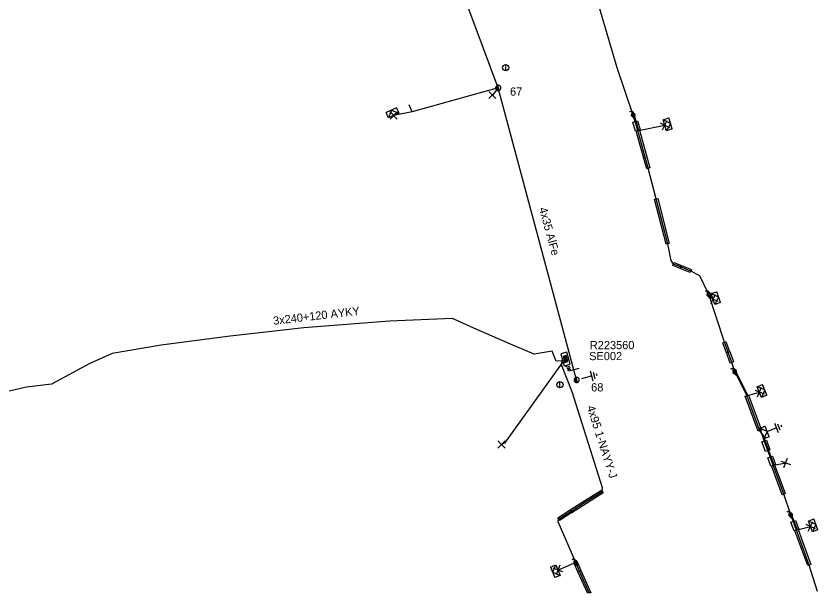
# Model space of a CAD drawing. Extents: x -536149 to -535465, y -1201639 to -1201298.
# Drawn here: x -535608.3 to -535510.8, y -1201637.8 to -1201567.7 of the extents above; entities that cross this region are included whole.
import ezdxf

# ---------------------------------------------------------------- set-up
doc = ezdxf.new("R2010")
doc.units = 0
for name, color, linetype in [('Vrstva 1', 7, 'Continuous'), ('Vrstva 10', 7, 'Continuous'), ('Vrstva 13', 7, 'Continuous'), ('Vrstva 14', 7, 'Continuous'), ('Vrstva 15', 7, 'Continuous'), ('Vrstva 18', 7, 'Continuous'), ('Vrstva 19', 7, 'Continuous'), ('Vrstva 2', 7, 'Continuous'), ('Vrstva 20', 7, 'Continuous'), ('Vrstva 28', 7, 'Continuous'), ('Vrstva 29', 7, 'Continuous'), ('Vrstva 30', 7, 'Continuous'), ('Vrstva 31', 7, 'Continuous'), ('Vrstva 34', 7, 'Continuous'), ('Vrstva 36', 7, 'Continuous'), ('Vrstva 4', 7, 'Continuous'), ('Vrstva 5', 7, 'Continuous'), ('Vrstva 52', 7, 'Continuous'), ('Vrstva 59', 7, 'Continuous'), ('Vrstva 6', 7, 'Continuous'), ('Vrstva 8', 7, 'Continuous'), ('Vrstva 9', 7, 'Continuous')]:
    doc.layers.add(name, color=color, linetype=linetype)

# ---------------------------------------------------------------- blocks, each defined once
blk = doc.blocks.new('NN440')
at = {"layer": 'Vrstva 2'}
for points in [[(0.63, 0), (0.63, 0.06), (0.62, 0.13), (0.6, 0.19), (0.58, 0.25), (0.55, 0.31), (0.51, 0.37), (0.47, 0.42), (0.42, 0.46), (0.37, 0.51), (0.32, 0.54), (0.26, 0.57), (0.2, 0.59), (0.13, 0.61), (0.07, 0.62), (0, 0.63), (-0.06, 0.62), (-0.13, 0.61), (-0.19, 0.59), (-0.26, 0.57), (-0.31, 0.54), (-0.37, 0.51), (-0.42, 0.46), (-0.47, 0.42), (-0.51, 0.37), (-0.54, 0.31), (-0.57, 0.25), (-0.6, 0.19), (-0.62, 0.13), (-0.63, 0.06), (-0.63, 0), (-0.63, -0.07), (-0.62, -0.14), (-0.6, -0.2), (-0.57, -0.26), (-0.54, -0.32), (-0.51, -0.37), (-0.47, -0.43), (-0.42, -0.47), (-0.37, -0.51), (-0.31, -0.55), (-0.26, -0.58), (-0.19, -0.6), (-0.13, -0.62), (-0.06, -0.63), (0, -0.63), (0.07, -0.63), (0.13, -0.62), (0.2, -0.6), (0.26, -0.58), (0.32, -0.55), (0.37, -0.51), (0.42, -0.47), (0.47, -0.43), (0.51, -0.37), (0.55, -0.32), (0.58, -0.26), (0.6, -0.2), (0.62, -0.14), (0.63, -0.07), (0.63, 0)], [(-0.63, 0), (0.63, 0)], [(-0.6, -0.18), (0.57, -0.18)], [(-0.51, -0.32), (0.5, -0.32)], [(-0.37, -0.47), (0.35, -0.47)]]:
    blk.add_lwpolyline(points, dxfattribs=at)
blk = doc.blocks.new('NN840')
at = {"layer": 'Vrstva 15'}
for points in [[(0.003, 0.619), (0.003, -0.631)], [(-0.745, -0.71), (-0.745, -0.66)], [(-0.73, -0.764), (-0.745, -0.71)], [(-0.657, -0.798), (-0.73, -0.764)], [(-0.627, -0.798), (-0.657, -0.798)], [(-0.558, -0.764), (-0.627, -0.798)], [(-0.538, -0.71), (-0.558, -0.764)], [(-0.538, -0.385), (-0.538, -0.71)], [(-0.332, -0.385), (-0.332, -0.798)], [(-0.332, -0.641), (-0.125, -0.385)], [(-0.263, -0.557), (-0.091, -0.798)]]:
    blk.add_lwpolyline(points, dxfattribs=at)
blk = doc.blocks.new('NN770')
at = {"layer": 'Vrstva 10'}
for p, q in [((0.002, 0.187), (0.002, 0.263)), ((0.002, -0.276), (0.002, 0.111))]:
    blk.add_line(p, q, dxfattribs=at)
blk.add_circle((0, -0.008), 0.375, dxfattribs=at)
blk = doc.blocks.new('NN880')
at = {"layer": 'Vrstva 4'}
for points in [[(0.001, 0.248), (-0.499, 0)], [(0.001, 0.185), (-0.373, 0)], [(0.001, 0.122), (-0.247, 0)], [(0.001, 0.059), (-0.125, 0)], [(0.501, 0), (0.001, 0.248)], [(0.375, 0), (0.001, 0.185)], [(0.249, 0), (0.001, 0.122)], [(0.127, 0), (0.001, 0.059)], [(-0.566, -0.13), (-0.436, -0.13)], [(-0.499, 0), (0.001, -0.252)], [(-0.499, -0.13), (-0.499, -0.327)], [(-0.373, 0), (0.001, -0.189)], [(-0.247, 0), (0.001, -0.126)], [(-0.125, 0), (0.001, -0.063)], [(0.001, -0.252), (0.501, 0)], [(0.001, -0.189), (0.375, 0)], [(0.001, -0.126), (0.249, 0)], [(0.001, -0.063), (0.127, 0)]]:
    blk.add_lwpolyline(points, dxfattribs=at)
blk = doc.blocks.new('NN800')
at = {"layer": 'Vrstva 1'}
for points in [[(-0.442, 0.442), (0.442, -0.442)], [(-0.442, -0.442), (0.442, 0.442)]]:
    blk.add_lwpolyline(points, dxfattribs=at)
blk = doc.blocks.new('NN620')
at = {"layer": 'Vrstva 8'}
for points in [[(0.752, 0.004), (-0.748, 0.004)], [(-0.748, 0.004), (-0.748, -0.746)], [(0.752, -0.746), (0.752, 0.004)], [(-0.748, -0.746), (0.752, -0.746)], [(0.368, -0.18), (-0.376, -0.18)], [(-0.376, -0.18), (-0.376, -0.558)], [(-0.376, -0.558), (0.368, -0.558)], [(0.321, -0.227), (-0.329, -0.227)], [(-0.329, -0.227), (-0.329, -0.51)], [(-0.329, -0.51), (0.321, -0.51)], [(0.274, -0.274), (-0.281, -0.274)], [(-0.281, -0.274), (-0.281, -0.463)], [(-0.281, -0.463), (0.274, -0.463)], [(0.227, -0.321), (-0.234, -0.321)], [(-0.234, -0.321), (-0.234, -0.416)], [(-0.234, -0.416), (0.227, -0.416)], [(-0.193, -0.369), (0.185, -0.369)], [(0.227, -0.416), (0.227, -0.321)], [(0.274, -0.463), (0.274, -0.274)], [(0.321, -0.51), (0.321, -0.227)], [(0.368, -0.558), (0.368, -0.18)]]:
    blk.add_lwpolyline(points, dxfattribs=at)
blk = doc.blocks.new('NN630')
at = {"layer": 'Vrstva 9'}
for points in [[(-0.003, -0.7), (-0.703, 0)], [(-0.703, -0.7), (-0.703, 0), (0.697, 0), (0.697, -0.7)], [(-0.703, -0.7), (0.697, -0.7)], [(-0.003, -0.7), (0.697, 0)]]:
    blk.add_lwpolyline(points, dxfattribs=at)
blk = doc.blocks.new('NN810')
at = {"layer": 'Vrstva 14'}
for points in [[(0.004, -0.64), (0.004, -1.89)], [(0.629, -1.89), (-0.621, -1.89)], [(0.388, -2.2), (-0.399, -2.2)], [(0.004, -2.515), (-0.124, -2.515)], [(0.137, -2.515), (0.004, -2.515)]]:
    blk.add_lwpolyline(points, dxfattribs=at)
blk = doc.blocks.new('NN510')
at = {"layer": 'Vrstva 2'}
blk.add_lwpolyline([(0.001, 0.002), (0.001, 0.939)], dxfattribs=at)

msp = doc.modelspace()

# ---------------------------------------------------------------- linework, layer by layer
at = {"layer": 'Vrstva 1'}
msp.add_lwpolyline([(-535540.143, -1201611.931), (-535549.68, -1201576.4), (-535561.545, -1201544.626)], dxfattribs=at)
at = {"layer": 'Vrstva 20'}
for points in [[(-535532.743, -1201580.414), (-535532.413, -1201581.514), (-535532.987, -1201581.686), (-535533.317, -1201580.586)], [(-535531.623, -1201586.243), (-535532.893, -1201581.653), (-535532.507, -1201581.547), (-535531.237, -1201586.137)], [(-535529.264, -1201595.43), (-535530.664, -1201589.96), (-535530.276, -1201589.86), (-535528.876, -1201595.33)], [(-535528.311, -1201597.652), (-535527.391, -1201597.992), (-535527.529, -1201598.368), (-535528.449, -1201598.028)], [(-535526.317, -1201598.875), (-535527.537, -1201598.365), (-535527.383, -1201597.995), (-535526.163, -1201598.505)], [(-535521.993, -1201607.268), (-535521.533, -1201608.468), (-535521.907, -1201608.612), (-535522.367, -1201607.412)], [(-535521.459, -1201609.877), (-535521.909, -1201608.607), (-535521.531, -1201608.473), (-535521.081, -1201609.743)], [(-535519.252, -1201613.761), (-535517.672, -1201618.031), (-535518.048, -1201618.169), (-535519.628, -1201613.899)], [(-535517.058, -1201619.247), (-535516.628, -1201620.417), (-535517.192, -1201620.623), (-535517.622, -1201619.453)], [(-535516.338, -1201621.179), (-535515.968, -1201622.209), (-535516.532, -1201622.411), (-535516.902, -1201621.381)], [(-535515.137, -1201625.88), (-535516.437, -1201622.38), (-535516.063, -1201622.24), (-535514.763, -1201625.74)], [(-535540.928, -1201627.731), (-535539.157, -1201626.601), (-535537.136, -1201625.331), (-535536.924, -1201625.669), (-535538.943, -1201626.939), (-535540.712, -1201628.069)], [(-535542.438, -1201628.702), (-535540.928, -1201627.732), (-535540.712, -1201628.068), (-535542.222, -1201629.038)], [(-535513.529, -1201629.015), (-535513.129, -1201630.085), (-535513.691, -1201630.295), (-535514.091, -1201629.225)], [(-535512.038, -1201634.509), (-535513.598, -1201630.259), (-535513.222, -1201630.121), (-535511.662, -1201634.371)], [(-535540.066, -1201634.051), (-535539.616, -1201635.101), (-535539.984, -1201635.259), (-535540.434, -1201634.209)], [(-535538.836, -1201637.835), (-535539.983, -1201635.261), (-535539.617, -1201635.099), (-535538.399, -1201637.832)]]:
    msp.add_lwpolyline(points, close=True, dxfattribs=at)
at = {"layer": 'Vrstva 5'}
for points in [[(-535510.853, -1201637.663), (-535511.85, -1201634.44), (-535513.41, -1201630.19), (-535514.11, -1201628.34), (-535514.95, -1201625.81), (-535516.25, -1201622.31), (-535516.62, -1201621.28), (-535517.34, -1201619.35), (-535517.62, -1201618.44), (-535517.86, -1201618.1), (-535519.44, -1201613.83), (-535520.91, -1201610.91), (-535521.27, -1201609.81), (-535521.72, -1201608.54), (-535522.18, -1201607.34), (-535524.06, -1201601.54), (-535525.16, -1201599.28), (-535526.24, -1201598.69), (-535527.46, -1201598.18), (-535528.38, -1201597.84), (-535528.66, -1201597.39), (-535529.07, -1201595.38), (-535530.47, -1201589.91), (-535531.43, -1201586.19), (-535532.7, -1201581.6), (-535533.26, -1201579.71), (-535535.21, -1201573.95), (-535537.66, -1201565.65)], [(-535541.81, -1201609.568), (-535541.94, -1201609.6), (-535542.62, -1201609.63), (-535543.14, -1201608.42), (-535545.31, -1201608.81), (-535548.18, -1201607.57), (-535552.64, -1201605.64), (-535555.25, -1201604.46), (-535562.9, -1201604.76), (-535573.31, -1201605.57), (-535582.28, -1201606.62), (-535590.67, -1201607.71), (-535596.64, -1201608.7), (-535599.34, -1201609.92), (-535604.02, -1201612.44), (-535607.05, -1201612.79), (-535608.95, -1201613.25), (-535609.8, -1201613.28), (-535609.91, -1201612.61), (-535609.923, -1201612.445)], [(-535538.617, -1201637.833), (-535539.8, -1201635.18), (-535540.25, -1201634.13), (-535542.38, -1201629.18), (-535542.33, -1201628.87), (-535540.82, -1201627.9), (-535539.05, -1201626.77), (-535537.03, -1201625.5), (-535536.98, -1201625.03), (-535540.69, -1201613.39), (-535541.98, -1201610.07), (-535541.85, -1201609.47)]]:
    msp.add_lwpolyline(points, dxfattribs=at)
at = {"layer": 'Vrstva 52'}
for points in [[(-535533.26, -1201579.71), (-535533.164, -1201579.682), (-535532.934, -1201580.472), (-535532.601, -1201581.58), (-535529.41, -1201580.94)], [(-535524.06, -1201601.54), (-535523.55, -1201602.08)], [(-535520.91, -1201610.91), (-535520.821, -1201610.865), (-535519.342, -1201613.802), (-535517.91, -1201613.4)], [(-535517.62, -1201618.44), (-535517.471, -1201618.585), (-535517.245, -1201619.318), (-535516.816, -1201620.485), (-535516.526, -1201621.245), (-535516.151, -1201622.291), (-535514.71, -1201622.01)], [(-535514.11, -1201628.34), (-535514.017, -1201628.304), (-535513.716, -1201629.085), (-535513.313, -1201630.164), (-535511.7, -1201629.74)], [(-535540.25, -1201634.13), (-535542.41, -1201635.05)]]:
    msp.add_lwpolyline(points, dxfattribs=at)
at = {"layer": 'Vrstva 59'}
for points in [[(-535549.68, -1201576.4), (-535550.393, -1201577.274)], [(-535541.747, -1201609.787), (-535541.905, -1201609.829), (-535548.92, -1201619.609), (-535549.274, -1201619.769)]]:
    msp.add_lwpolyline(points, dxfattribs=at)
at = {"layer": 'Vrstva 8'}
msp.add_lwpolyline([(-535549.68, -1201576.4), (-535560.156, -1201579.338), (-535562.398, -1201579.752)], dxfattribs=at)

# ---------------------------------------------------------------- block references
at = {"layer": 'Vrstva 13', "xscale": 0.5}
for p, yscale, rotation in [((-535549.681, -1201576.401), 0.5, -74.97204328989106), ((-535540.143, -1201611.931), 0.49999999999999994, -74.66063332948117)]:
    msp.add_blockref('NN440', p, dxfattribs=dict(at, yscale=yscale, rotation=rotation))
at = {"layer": 'Vrstva 13', "rotation": 23.575777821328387}
msp.add_blockref('NN510', (-535560.156, -1201579.338), dxfattribs=at)
at = {"layer": 'Vrstva 15'}
for p, rotation in [((-535540.143, -1201611.931), 105.08484482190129), ((-535517.62, -1201618.44), 111.25050554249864)]:
    msp.add_blockref('NN810', p, dxfattribs=dict(at, rotation=rotation))
at = {"layer": 'Vrstva 18', "rotation": -74.91515517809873}
msp.add_blockref('NN840', (-535540.477, -1201610.693), dxfattribs=at)
at = {"layer": 'Vrstva 19'}
for p, rotation in [((-535533.26, -1201579.71), -73.4956386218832), ((-535524.06, -1201601.54), -72.04052390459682), ((-535520.91, -1201610.91), -63.278189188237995), ((-535514.11, -1201628.34), -69.27444117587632), ((-535540.25, -1201634.13), -66.8014094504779)]:
    msp.add_blockref('NN880', p, dxfattribs=dict(at, rotation=rotation))
at = {"layer": 'Vrstva 28', "rotation": 105.02654440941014}
msp.add_blockref('NN620', (-535541.86, -1201609.469), dxfattribs=at)
at = {"layer": 'Vrstva 31'}
for p, rotation in [((-535562.398, -1201579.752), -156.26956385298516), ((-535529.41, -1201580.94), 107.36766352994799), ((-535523.55, -1201602.08), 108.32943184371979), ((-535517.91, -1201613.4), 112.15896377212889), ((-535517.62, -1201618.44), 111.25050554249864), ((-535511.7, -1201629.74), 110.947730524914), ((-535542.41, -1201635.05), -66.87801251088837)]:
    msp.add_blockref('NN630', p, dxfattribs=dict(at, rotation=rotation))
at = {"layer": 'Vrstva 34'}
for p in [(-535550.393, -1201577.274), (-535562.398, -1201579.752), (-535549.274, -1201619.769)]:
    msp.add_blockref('NN800', p, dxfattribs=at)
for p, rotation in [((-535529.41, -1201580.94), 17.59463414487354), ((-535523.55, -1201602.08), 18.800764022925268), ((-535517.91, -1201613.4), 23.30469923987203), ((-535514.71, -1201622.01), 24.368116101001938), ((-535511.7, -1201629.74), 19.72061178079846), ((-535542.41, -1201635.05), -156.82749636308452)]:
    msp.add_blockref('NN800', p, dxfattribs=dict(at, rotation=rotation))
at = {"layer": 'Vrstva 36'}
for p in [(-535548.773, -1201573.949), (-535542.17, -1201612.486)]:
    msp.add_blockref('NN770', p, dxfattribs=at)

# ---------------------------------------------------------------- texts
at = {"layer": 'Vrstva 14'}
for s, p in [('67', (-535548.242, -1201577.35)), ('68', (-535538.377, -1201613.325))]:
    msp.add_text(s, height=1, dxfattribs=at).set_placement(p)
at = {"layer": 'Vrstva 2'}
msp.add_text('4x35 AlFe', height=1, rotation=285.276, dxfattribs=at).set_placement((-535544.736, -1201591.074))
at = {"layer": 'Vrstva 29'}
msp.add_text('R223560', height=1, dxfattribs=at).set_placement((-535538.543, -1201608.187))
at = {"layer": 'Vrstva 30'}
msp.add_text('SE002', height=1, dxfattribs=at).set_placement((-535538.624, -1201609.52))
at = {"layer": 'Vrstva 6'}
for s, rotation, p in [('3x240+120 AYKY', 6.676, (-535576.999, -1201605.229)), ('4x95 1-NAYY-J', 287.679, (-535538.927, -1201615.206))]:
    msp.add_text(s, height=1, rotation=rotation, dxfattribs=at).set_placement(p)

doc.saveas('drawing.dxf')
